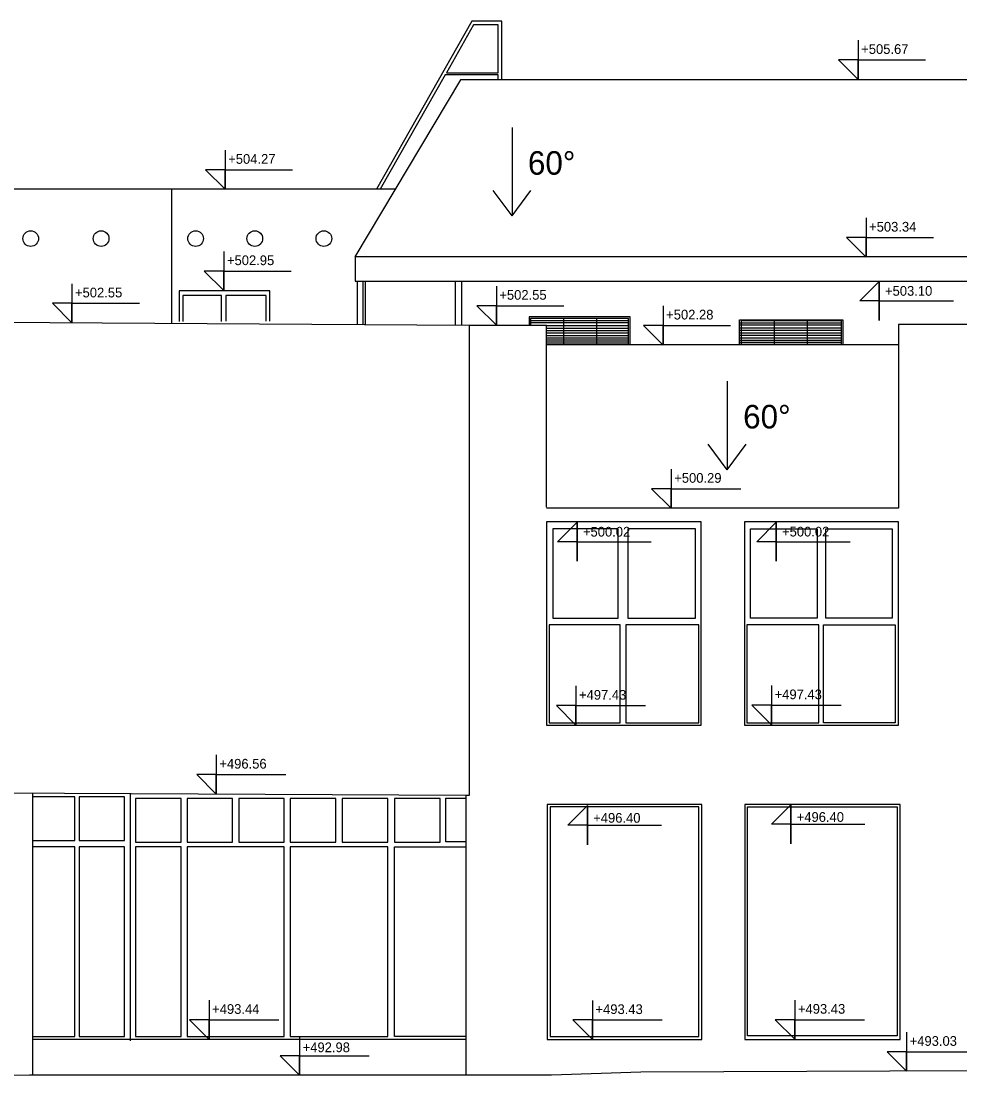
# Model space of a CAD drawing. Extents: x 3.3 to 94, y 492.8 to 514.5.
# Drawn here: x 42.57 to 54.56, y 492.94 to 506.42 of the extents above; entities that cross this region are included whole.
import ezdxf

# ---------------------------------------------------------------- set-up
doc = ezdxf.new("R2010")
doc.units = 0
for name, color, linetype in [('okap', 7, 'Continuous'), ('okna', 7, 'Continuous'), ('strecha_sikma', 7, 'Continuous'), ('teren', 7, 'Continuous'), ('vyustky_vzduchotechniky', 7, 'Continuous'), ('zakl_tenka', 7, 'Continuous'), ('zebrik', 7, 'Continuous'), ('znaceni', 7, 'Continuous')]:
    doc.layers.add(name, color=color, linetype=linetype)

msp = doc.modelspace()

# ---------------------------------------------------------------- linework, layer by layer
at = {"layer": 'okap'}
msp.add_lwpolyline([(63.644, 503.415), (46.838, 503.415), (46.838, 503.105), (63.644, 503.105)], close=True, dxfattribs=at)
for points in [[(46.871, 502.548), (46.871, 503.105)], [(46.943, 502.547), (46.943, 503.105)], [(48.116, 503.105), (48.116, 502.54)], [(48.203, 502.539), (48.203, 503.105)]]:
    msp.add_lwpolyline(points, dxfattribs=at)
at = {"layer": 'okna'}
msp.add_line((43.967, 496.556), (43.967, 493.401), dxfattribs=at)
for points in [[(45.134, 502.59), (45.134, 502.92), (44.64, 502.92), (44.64, 502.588)], [(45.702, 502.593), (45.702, 502.92), (45.186, 502.92), (45.186, 502.591)], [(42.719, 495.961), (43.259, 495.961), (43.259, 496.518), (42.719, 496.518)], [(48.253, 495.946), (47.998, 495.946), (47.998, 496.503), (48.253, 496.503)], [(42.719, 493.457), (43.259, 493.457), (43.259, 495.878), (42.719, 495.878)], [(48.253, 493.457), (47.343, 493.457), (47.343, 495.878), (48.253, 495.878)]]:
    msp.add_lwpolyline(points, dxfattribs=at)
for points in [[(50.199, 499.94), (49.363, 499.94), (49.363, 498.798), (50.199, 498.798)], [(51.187, 499.94), (50.322, 499.94), (50.322, 498.798), (51.187, 498.798)], [(51.888, 499.94), (52.739, 499.94), (52.739, 498.798), (51.888, 498.798)], [(52.85, 499.94), (53.699, 499.94), (53.699, 498.798), (52.85, 498.798)], [(50.226, 498.715), (49.317, 498.715), (49.317, 497.465), (50.226, 497.465)], [(50.295, 497.465), (51.228, 497.465), (51.228, 498.715), (50.295, 498.715)], [(52.762, 498.714), (51.844, 498.714), (51.844, 497.465), (52.762, 497.465)], [(52.821, 498.714), (53.735, 498.714), (53.735, 497.465), (52.821, 497.465)], [(43.895, 496.518), (43.315, 496.518), (43.315, 495.961), (43.895, 495.961)], [(44.617, 496.498), (44.036, 496.498), (44.036, 495.941), (44.617, 495.941)], [(45.273, 496.498), (44.692, 496.498), (44.692, 495.941), (45.273, 495.941)], [(45.932, 496.498), (45.352, 496.498), (45.352, 495.941), (45.932, 495.941)], [(46.591, 496.498), (46.01, 496.498), (46.01, 495.941), (46.591, 495.941)], [(47.255, 496.498), (46.674, 496.498), (46.674, 495.941), (47.255, 495.941)], [(47.924, 496.498), (47.343, 496.498), (47.343, 495.941), (47.924, 495.941)], [(51.23, 496.389), (49.329, 496.389), (49.329, 493.457), (51.23, 493.457)], [(53.762, 493.465), (51.849, 493.465), (51.849, 496.389), (53.762, 496.389)], [(43.895, 495.878), (43.315, 495.878), (43.315, 493.457), (43.895, 493.457)], [(44.617, 495.878), (44.036, 495.878), (44.036, 493.457), (44.617, 493.457)], [(45.932, 495.878), (44.692, 495.878), (44.692, 493.457), (45.932, 493.457)], [(47.255, 495.878), (46.011, 495.878), (46.011, 493.457), (47.255, 493.457)]]:
    msp.add_lwpolyline(points, close=True, dxfattribs=at)
at = {"layer": 'strecha_sikma'}
for p, q in [((48.184, 505.676), (46.835, 503.415)), ((62.124, 505.676), (48.184, 505.676)), ((63.644, 503.415), (46.835, 503.415)), ((53.781, 502.289), (49.284, 502.289)), ((53.781, 500.203), (49.284, 500.203))]:
    msp.add_line(p, q, dxfattribs=at)
at = {"layer": 'teren'}
for p, q in [((54.731, 493.02), (50.487, 493.004)), ((42.678, 492.964), (40.456, 492.943)), ((49.349, 492.963), (42.678, 492.964)), ((50.487, 493.004), (49.349, 492.963))]:
    msp.add_line(p, q, dxfattribs=at)
at = {"layer": 'vyustky_vzduchotechniky'}
for p, q in [((49.071, 502.602), (50.331, 502.602)), ((49.499, 502.628), (49.499, 502.289)), ((49.924, 502.628), (49.924, 502.289)), ((52.193, 502.595), (52.193, 502.289)), ((52.611, 502.595), (52.611, 502.289)), ((49.07, 502.574), (50.331, 502.574)), ((49.284, 502.539), (50.331, 502.539)), ((49.284, 502.505), (50.331, 502.505)), ((49.284, 502.473), (50.331, 502.473)), ((51.75, 502.573), (53.052, 502.573)), ((51.75, 502.545), (53.052, 502.545)), ((51.75, 502.509), (53.052, 502.509)), ((51.75, 502.476), (53.052, 502.476)), ((49.284, 502.443), (50.331, 502.443)), ((49.284, 502.41), (50.331, 502.41)), ((49.284, 502.38), (50.331, 502.38)), ((49.284, 502.355), (50.331, 502.355)), ((49.284, 502.328), (50.331, 502.328)), ((51.75, 502.443), (53.052, 502.443)), ((51.75, 502.414), (53.052, 502.414)), ((51.75, 502.381), (53.052, 502.381)), ((51.75, 502.351), (53.052, 502.351)), ((51.75, 502.325), (53.052, 502.325)), ((49.284, 502.304), (50.331, 502.304)), ((51.75, 502.299), (53.052, 502.299))]:
    msp.add_line(p, q, dxfattribs=at)
for points in [[(50.35, 502.289), (50.35, 502.646), (49.06, 502.646), (49.06, 502.539)], [(50.331, 502.289), (50.331, 502.628), (49.079, 502.628), (49.079, 502.539)], [(51.75, 502.289), (51.75, 502.608), (53.067, 502.608), (53.067, 502.289)], [(53.052, 502.289), (53.052, 502.595), (51.768, 502.595), (51.768, 502.289)]]:
    msp.add_lwpolyline(points, dxfattribs=at)
at = {"layer": 'zakl_tenka'}
for p, q in [((47.349, 504.278), (32.24, 504.278)), ((44.492, 504.278), (44.492, 502.563)), ((46.966, 503.105), (46.966, 502.547)), ((48.295, 502.539), (41.755, 502.58)), ((49.284, 502.539), (48.295, 502.539)), ((48.295, 502.539), (48.295, 496.536)), ((49.284, 500.217), (49.284, 502.539)), ((56.766, 502.551), (53.781, 502.551)), ((53.781, 502.551), (53.781, 500.203)), ((48.253, 496.536), (41.713, 496.567)), ((42.719, 496.557), (42.719, 492.964)), ((48.295, 496.536), (48.253, 496.536)), ((48.253, 496.536), (48.253, 492.963)), ((48.253, 493.419), (42.719, 493.419))]:
    msp.add_line(p, q, dxfattribs=at)
msp.add_lwpolyline([(45.751, 502.593), (45.751, 502.978), (44.593, 502.978), (44.593, 502.588)], dxfattribs=at)
for points in [[(51.259, 500.03), (49.283, 500.03), (49.283, 497.434), (51.259, 497.434)], [(53.778, 500.03), (51.813, 500.03), (51.813, 497.434), (53.778, 497.434)], [(51.267, 496.42), (49.294, 496.42), (49.294, 493.419), (51.267, 493.419)], [(53.802, 496.42), (51.815, 496.42), (51.815, 493.419), (53.802, 493.419)]]:
    msp.add_lwpolyline(points, close=True, dxfattribs=at)
for centre in [(42.695, 503.647), (43.595, 503.647), (43.595, 503.647), (44.802, 503.647), (45.558, 503.647), (46.44, 503.647)]:
    msp.add_circle(centre, 0.1, dxfattribs=at)
at = {"layer": 'zebrik'}
for p, q in [((48.33, 506.424), (47.112, 504.278)), ((48.353, 506.378), (48.005, 505.765)), ((48.712, 506.424), (48.33, 506.424)), ((48.668, 506.378), (48.353, 506.378)), ((48.668, 505.765), (48.668, 506.378)), ((48.712, 505.676), (48.712, 506.424)), ((47.991, 505.74), (47.161, 504.278)), ((48.668, 505.676), (48.668, 505.74))]:
    msp.add_line(p, q, dxfattribs=at)
for points in [[(48.668, 505.74), (47.991, 505.74)], [(48.005, 505.765), (48.668, 505.765)]]:
    msp.add_lwpolyline(points, dxfattribs=at)
at = {"layer": 'znaceni'}
for p, q in [((53.264, 506.179), (53.264, 505.679)), ((53.264, 505.929), (53.014, 505.929)), ((53.014, 505.929), (53.264, 505.679)), ((53.264, 505.679), (53.264, 505.929)), ((53.264, 505.929), (54.123, 505.929)), ((48.843, 505.066), (48.843, 503.936)), ((45.179, 504.776), (45.179, 504.276)), ((45.179, 504.526), (44.929, 504.526)), ((44.929, 504.526), (45.179, 504.276)), ((45.179, 504.276), (45.179, 504.526)), ((45.179, 504.526), (46.04, 504.526)), ((48.843, 503.936), (48.602, 504.263)), ((48.843, 503.936), (49.084, 504.263)), ((53.365, 503.91), (53.365, 503.41)), ((53.365, 503.66), (53.115, 503.66)), ((53.115, 503.66), (53.365, 503.41)), ((53.365, 503.41), (53.365, 503.66)), ((53.365, 503.66), (54.225, 503.66)), ((45.163, 503.482), (45.163, 502.982)), ((45.163, 503.232), (44.913, 503.232)), ((44.913, 503.232), (45.163, 502.982)), ((45.163, 502.982), (45.163, 503.232)), ((45.163, 503.232), (46.024, 503.232)), ((43.222, 503.071), (43.222, 502.571)), ((48.643, 503.04), (48.643, 502.54)), ((53.284, 502.851), (53.534, 503.101)), ((53.534, 503.101), (53.534, 502.601)), ((53.534, 502.601), (53.534, 503.101)), ((53.534, 503.101), (53.534, 502.851)), ((43.222, 502.821), (42.972, 502.821)), ((42.972, 502.821), (43.222, 502.571)), ((43.222, 502.571), (43.222, 502.821)), ((43.222, 502.821), (44.083, 502.821)), ((48.643, 502.79), (48.393, 502.79)), ((48.393, 502.79), (48.643, 502.54)), ((48.643, 502.54), (48.643, 502.79)), ((48.643, 502.79), (49.504, 502.79)), ((50.773, 502.788), (50.773, 502.288)), ((53.534, 502.851), (53.284, 502.851)), ((53.534, 502.851), (53.284, 502.851)), ((53.534, 502.601), (53.534, 502.851)), ((53.534, 502.851), (54.48, 502.851)), ((53.534, 502.851), (54.48, 502.851)), ((50.773, 502.538), (50.523, 502.538)), ((50.523, 502.538), (50.773, 502.288)), ((50.773, 502.288), (50.773, 502.538)), ((50.773, 502.538), (51.634, 502.538)), ((51.591, 501.825), (51.591, 500.695)), ((51.591, 500.695), (51.35, 501.022)), ((51.591, 500.695), (51.832, 501.022)), ((50.876, 500.703), (50.876, 500.203)), ((50.876, 500.453), (50.626, 500.453)), ((50.626, 500.453), (50.876, 500.203)), ((50.876, 500.203), (50.876, 500.453)), ((50.876, 500.453), (51.766, 500.453)), ((49.426, 499.776), (49.676, 500.026)), ((49.676, 500.026), (49.676, 499.526)), ((49.676, 499.526), (49.676, 500.026)), ((49.676, 500.026), (49.676, 499.776)), ((51.969, 499.776), (52.219, 500.026)), ((52.219, 500.026), (52.219, 499.526)), ((52.219, 499.526), (52.219, 500.026)), ((52.219, 500.026), (52.219, 499.776)), ((49.676, 499.776), (49.426, 499.776)), ((49.676, 499.776), (49.426, 499.776)), ((49.676, 499.526), (49.676, 499.776)), ((49.676, 499.776), (50.622, 499.776)), ((49.676, 499.776), (50.622, 499.776)), ((52.219, 499.776), (51.969, 499.776)), ((52.219, 499.776), (51.969, 499.776)), ((52.219, 499.526), (52.219, 499.776)), ((52.219, 499.776), (53.164, 499.776)), ((52.219, 499.776), (53.164, 499.776)), ((49.66, 497.934), (49.66, 497.434)), ((52.158, 497.939), (52.158, 497.439)), ((49.66, 497.684), (49.41, 497.684)), ((49.41, 497.684), (49.66, 497.434)), ((49.66, 497.434), (49.66, 497.684)), ((49.66, 497.684), (50.55, 497.684)), ((52.158, 497.689), (51.908, 497.689)), ((51.908, 497.689), (52.158, 497.439)), ((52.158, 497.439), (52.158, 497.689)), ((52.158, 497.689), (53.048, 497.689)), ((45.066, 497.053), (45.066, 496.553)), ((45.066, 496.803), (44.816, 496.803)), ((44.816, 496.803), (45.066, 496.553)), ((45.066, 496.553), (45.066, 496.803)), ((45.066, 496.803), (45.956, 496.803)), ((49.557, 496.157), (49.807, 496.407)), ((49.807, 496.407), (49.807, 495.907)), ((49.807, 495.907), (49.807, 496.407)), ((49.807, 496.407), (49.807, 496.157)), ((52.156, 496.168), (52.406, 496.418)), ((52.406, 496.418), (52.406, 495.918)), ((52.406, 495.918), (52.406, 496.418)), ((52.406, 496.418), (52.406, 496.168)), ((49.807, 496.157), (49.557, 496.157)), ((49.807, 496.157), (49.557, 496.157)), ((49.807, 495.907), (49.807, 496.157)), ((49.807, 496.157), (50.752, 496.157)), ((49.807, 496.157), (50.752, 496.157)), ((52.406, 496.168), (52.156, 496.168)), ((52.406, 496.168), (52.156, 496.168)), ((52.406, 495.918), (52.406, 496.168)), ((52.406, 496.168), (53.351, 496.168)), ((52.406, 496.168), (53.351, 496.168)), ((44.974, 493.921), (44.974, 493.421)), ((49.87, 493.92), (49.87, 493.42)), ((52.456, 493.923), (52.456, 493.423)), ((44.974, 493.671), (44.724, 493.671)), ((44.724, 493.671), (44.974, 493.421)), ((44.974, 493.421), (44.974, 493.671)), ((44.974, 493.671), (45.864, 493.671)), ((49.87, 493.67), (49.62, 493.67)), ((49.62, 493.67), (49.87, 493.42)), ((49.87, 493.42), (49.87, 493.67)), ((49.87, 493.67), (50.76, 493.67)), ((52.456, 493.673), (52.206, 493.673)), ((52.206, 493.673), (52.456, 493.423)), ((52.456, 493.423), (52.456, 493.673)), ((52.456, 493.673), (53.346, 493.673)), ((46.13, 493.463), (46.13, 492.963)), ((53.883, 493.514), (53.883, 493.014)), ((46.13, 493.213), (45.88, 493.213)), ((45.88, 493.213), (46.13, 492.963)), ((46.13, 492.963), (46.13, 493.213)), ((46.13, 493.213), (47.02, 493.213)), ((53.883, 493.264), (53.633, 493.264)), ((53.633, 493.264), (53.883, 493.014)), ((53.883, 493.014), (53.883, 493.264)), ((53.883, 493.264), (54.772, 493.264))]:
    msp.add_line(p, q, dxfattribs=at)

# ---------------------------------------------------------------- texts
for s, height, p in [('+505.67', 0.124, (53.303, 506.005)), ('60°', 0.3, (49.046, 504.463)), ('+504.27', 0.124, (45.218, 504.602)), ('+503.34', 0.124, (53.404, 503.736)), ('+502.95', 0.124, (45.202, 503.308)), ('+502.55', 0.124, (43.261, 502.896)), ('+502.55', 0.124, (48.681, 502.866)), ('+503.10', 0.124, (53.607, 502.917)), ('+502.28', 0.124, (50.812, 502.614)), ('60°', 0.3, (51.795, 501.223)), ('+500.29', 0.124, (50.915, 500.529)), ('+500.02', 0.124, (49.749, 499.842)), ('+500.02', 0.124, (52.292, 499.843)), ('+497.43', 0.124, (49.699, 497.759)), ('+497.43', 0.124, (52.197, 497.765)), ('+496.56', 0.124, (45.105, 496.879)), ('+496.40', 0.124, (49.88, 496.188)), ('+496.40', 0.124, (52.479, 496.199)), ('+493.44', 0.124, (45.013, 493.747)), ('+493.43', 0.124, (49.909, 493.745)), ('+493.43', 0.124, (52.495, 493.749)), ('+493.03', 0.124, (53.922, 493.339)), ('+492.98', 0.124, (46.169, 493.258))]:
    msp.add_text(s, height=height, dxfattribs=at).set_placement(p)

doc.saveas('drawing.dxf')
